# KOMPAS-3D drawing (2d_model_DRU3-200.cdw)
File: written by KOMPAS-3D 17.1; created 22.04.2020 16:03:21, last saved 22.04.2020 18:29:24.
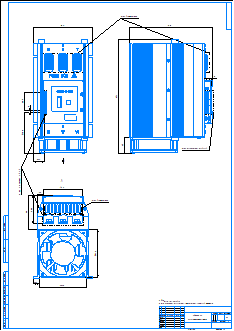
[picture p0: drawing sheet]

Sheet 1: A1, portrait

Title block, sheet 1: name: DRU3-200 / Габаритный чертеж; sheets: 1; sheet format: A1; stored path: E:\Марк\DRU3\DRU3-XX\2d_model_DRU3-200.cdw

Views: Вид по стрелке 4
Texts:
  Пользователь Windows
  ·зЙИ
  НвїЗЈЁ7.27Ј©
  ИэПаЅУПЯ¶ЛЧУ
  ЛДПаЅУПЯ¶ЛЧУ
  РЎПЯВ·°еЈЁ0Ј©
  Гж°еЧйєП(7.27)
  ВЭДё
  M4ВЭЛї
  ВЭДёС№Ж¬
  ВЭЛї
  µжЖ¬
  M8ВЭЛїЧйєП
  M4ВЭЛї(0)
  M3-10ЖЅН·ВЭЛї
  M3ВЭЛї(0)
  M4ВЭЛї(і¤)
Dimensions and other numbers on the sheet: 1:1; 1; 200AЙўИИЖч(0); 200AІа°е(0); 200AЦ§јЬ(0); 200AєуёЗ(1); 200AHHT3µчЅЪїЄ№ШPCB(0); 200AєуёЗ(0); 200AИэПаµзБ¦µчХыЖч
